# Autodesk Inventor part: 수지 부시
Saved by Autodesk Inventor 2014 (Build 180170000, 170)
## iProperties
Created: 2025-06
Part Number: 수지 부시
Material: 일반
Document SubType Name: Modeling
Designer: dg
Density: 1 g/cm^3
Appearance: 기본값
Author: dg
Author: jhkim
Creation Date: 2025-05-27
Sending System: Autodesk Inventor 2026
Preprocessor: ST-DEVELOPER v20.1
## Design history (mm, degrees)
node "수지 부시1"
node "솔리드1"
node "기준1"
